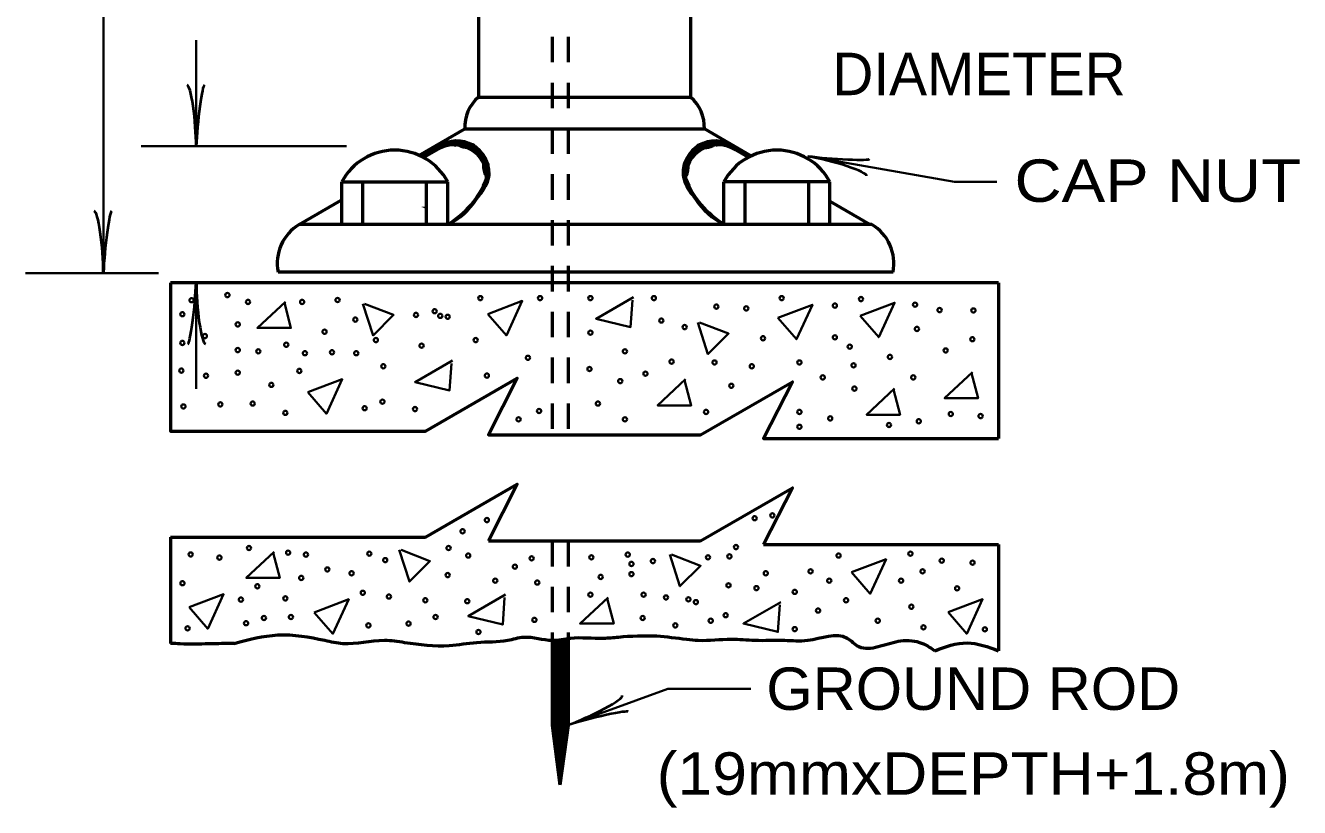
# Model space of a CAD drawing. Extents: x -761 to 95, y 34 to 578.
# Drawn here: x -554.6 to -482.6, y 285.9 to 330.2 of the extents above; entities that cross this region are included whole.
import ezdxf
from ezdxf.enums import TextEntityAlignment as Align

# ---------------------------------------------------------------- set-up
doc = ezdxf.new("R2010")
doc.units = 0
doc.header["$LTSCALE"] = 0.96
doc.linetypes.add('SHORT_DASHED', pattern=[2.7, 1.5, -1.2])
doc.layers.add('1', color=7, linetype='Continuous', lineweight=53)

msp = doc.modelspace()

# ---------------------------------------------------------------- linework, layer by layer
at = {"layer": '1'}
for p, q in [((-517.0193, 467.7038), (-517.0193, 326.125)), ((-529.0193, 336.7251), (-529.0193, 326.125)), ((-529.0193, 326.125), (-517.0193, 326.125)), ((-532.3876, 322.8281), (-529.7949, 324.325)), ((-529.7949, 324.325), (-516.2437, 324.325)), ((-513.6183, 322.8092), (-516.2437, 324.325)), ((-532.2425, 322.7735), (-531.2352, 323.3551)), ((-532.129, 322.7734), (-531.1792, 323.3218)), ((-532.1165, 322.7517), (-531.1667, 323.3001)), ((-532.098, 322.7197), (-531.1482, 323.2681)), ((-513.7656, 322.7197), (-514.7154, 323.2681)), ((-513.7471, 322.7517), (-514.6969, 323.3001)), ((-513.7346, 322.7734), (-514.6844, 323.3218)), ((-513.6211, 322.7735), (-514.6284, 323.3551)), ((-536.748, 318.925), (-536.748, 321.325)), ((-536.748, 321.325), (-530.748, 321.325)), ((-535.548, 318.925), (-535.548, 321.325)), ((-531.948, 318.925), (-531.948, 321.325)), ((-530.748, 318.925), (-530.748, 321.325)), ((-515.1456, 318.925), (-515.1456, 321.325)), ((-509.1456, 321.325), (-515.1456, 321.325)), ((-513.9456, 318.925), (-513.9456, 321.325)), ((-510.3456, 318.925), (-510.3456, 321.325)), ((-509.1456, 318.925), (-509.1456, 321.325)), ((-539.148, 318.925), (-536.7713, 320.2972)), ((-506.8906, 318.925), (-509.1351, 320.2208)), ((-506.7746, 318.925), (-539.148, 318.925)), ((-505.5746, 316.225), (-540.348, 316.225)), ((-499.6193, 315.625), (-546.4193, 315.625)), ((-499.6193, 315.625), (-499.6193, 306.8098)), ((-546.4193, 301.225), (-532.0193, 301.225)), ((-546.4193, 301.225), (-546.4193, 295.225)), ((-528.4575, 301.0174), (-516.4575, 301.0174)), ((-512.8957, 300.8098), (-499.6193, 300.8098)), ((-499.6193, 300.8098), (-499.6193, 294.8098)), ((-524.8487, 295.4027), (-524.8487, 290.6027)), ((-524.8059, 295.4027), (-524.8059, 290.2684)), ((-524.7608, 295.4027), (-524.7608, 289.9162)), ((-524.7157, 295.4027), (-524.7157, 289.564)), ((-524.6706, 295.4027), (-524.6706, 289.2118)), ((-524.6255, 295.4027), (-524.6255, 288.8596)), ((-524.5954, 295.4027), (-524.5954, 288.6245)), ((-524.5503, 295.4027), (-524.5503, 288.2723)), ((-524.5202, 295.4027), (-524.5202, 288.0372)), ((-524.4751, 295.4027), (-524.4751, 287.685)), ((-524.43, 295.4027), (-524.43, 287.3328)), ((-524.3999, 295.4027), (-524.3999, 287.3239)), ((-524.3698, 295.4027), (-524.3698, 287.5426)), ((-524.3247, 295.4027), (-524.3247, 287.8704)), ((-524.2946, 295.4027), (-524.2946, 288.0891)), ((-524.2495, 295.4027), (-524.2495, 288.4168)), ((-524.1894, 295.4027), (-524.1894, 288.8536)), ((-524.1443, 295.4027), (-524.1443, 289.1813)), ((-524.1142, 295.4027), (-524.1142, 289.4)), ((-524.054, 295.4027), (-524.054, 289.8375)), ((-524.024, 295.4027), (-524.024, 290.0555)), ((-523.9487, 295.5049), (-523.9487, 290.6027)), ((-524.8487, 290.6027), (-524.4149, 287.2149)), ((-523.9487, 290.6027), (-524.4149, 287.2149))]:
    msp.add_line(p, q, dxfattribs=at)
at = {"layer": '1', "lineweight": 35}
for p, q in [((-550.2198, 389.2266), (-550.2198, 316.225)), ((-544.9735, 323.3548), (-544.9735, 329.3548)), ((-536.4826, 323.3548), (-548.0895, 323.3548)), ((-547.1104, 316.1577), (-554.6258, 316.1577)), ((-544.9735, 315.625), (-544.9735, 309.625))]:
    msp.add_line(p, q, dxfattribs=at)
at = {"layer": '1', "linetype": 'SHORT_DASHED'}
for p, q in [((-524.8487, 332.125), (-524.8487, 307.0174)), ((-523.9487, 332.125), (-523.9487, 307.0174)), ((-524.8487, 301.0174), (-524.8487, 295.4027)), ((-523.9487, 301.0174), (-523.9487, 295.5049))]:
    msp.add_line(p, q, dxfattribs=at)
at = {"layer": '1', "linetype": 'SHORT_DASHED', "lineweight": 13}
for p, q in [((-524.8487, 307.0174), (-524.8487, 306.9881)), ((-523.9487, 307.0174), (-523.9487, 306.9881))]:
    msp.add_line(p, q, dxfattribs=at)
at = {"layer": '1', "lineweight": 13}
for p, q in [((-524.3987, 290.6027), (-524.3987, 291.0254)), ((-524.8487, 290.6027), (-523.9487, 290.6027)), ((-524.4149, 290.8149), (-524.4149, 287.2149))]:
    msp.add_line(p, q, dxfattribs=at)
at = {"layer": '1', "lineweight": 35}
for points in [[(-510.3841, 322.7822), (-502.1117, 321.3236), (-499.7117, 321.3236)], [(-520.2596, 314.8049), (-522.3694, 313.5918), (-520.4178, 313.1171), (-520.3123, 314.6467)], [(-539.9335, 314.5412), (-541.5158, 313.0643), (-539.617, 313.0643), (-539.9862, 314.4884)], [(-535.5557, 314.4357), (-534.9755, 312.6424), (-533.8151, 313.8028), (-535.4502, 314.4357)], [(-516.6202, 313.3808), (-516.04, 311.5875), (-514.8796, 312.7479), (-516.5147, 313.3808)], [(-530.4921, 311.2183), (-532.6019, 310.0052), (-530.6503, 309.5305), (-530.5448, 311.0601)], [(-501.0824, 310.5641), (-502.6647, 309.0872), (-500.7659, 309.0872), (-501.1351, 310.5113)], [(-517.3059, 310.1634), (-518.8882, 308.6865), (-516.9894, 308.6865), (-517.3586, 310.1106)], [(-505.4911, 309.6359), (-507.0734, 308.159), (-505.1746, 308.159), (-505.5438, 309.5831)], [(-540.5664, 300.4056), (-542.1487, 298.9287), (-540.2499, 298.9287), (-540.6191, 300.3528)], [(-533.4985, 300.511), (-532.9183, 298.7177), (-531.7579, 299.8781), (-533.393, 300.511)], [(-518.2025, 300.2473), (-517.6223, 298.454), (-516.4619, 299.6144), (-518.097, 300.2473)], [(-527.4857, 297.9793), (-529.5955, 296.7662), (-527.6439, 296.2915), (-527.5384, 297.8211)], [(-521.6838, 297.8211), (-523.2661, 296.3442), (-521.3673, 296.3442), (-521.7365, 297.7683)], [(-511.926, 297.5573), (-514.0358, 296.3442), (-512.0842, 295.8695), (-511.9787, 297.3991)], [(-523.9487, 290.6027), (-518.3105, 292.6548), (-513.6138, 292.6548)]]:
    msp.add_lwpolyline(points, dxfattribs=at)
at = {"layer": '1'}
for points in [[(-546.4193, 315.625), (-546.4193, 307.225), (-532.0193, 307.225), (-526.8231, 310.225), (-528.4575, 307.0174), (-516.4575, 307.0174), (-511.2613, 310.0174), (-512.8957, 306.8098), (-499.6193, 306.8098)], [(-516.4575, 307.0174), (-511.2613, 310.0174), (-512.8957, 306.8098)], [(-532.0193, 301.225), (-526.8231, 304.225), (-528.4575, 301.0174)], [(-516.4575, 301.0174), (-511.2613, 304.0174), (-512.8957, 300.8098)]]:
    msp.add_lwpolyline(points, dxfattribs=at)
at = {"layer": '1', "lineweight": 35}
for points in [[(-528.4878, 313.8555), (-527.4329, 312.6424), (-526.5362, 314.594)], [(-512.0842, 313.6446), (-511.0293, 312.4315), (-510.1326, 314.3831)], [(-507.4426, 313.7499), (-506.3877, 312.5368), (-505.491, 314.4884)], [(-538.6676, 309.4249), (-537.6127, 308.2118), (-536.716, 310.1634)], [(-507.9174, 299.2451), (-506.8625, 298.032), (-505.9658, 299.9836)], [(-545.3755, 297.2671), (-544.3206, 296.054), (-543.4239, 298.0056)], [(-538.2984, 296.9771), (-537.2435, 295.764), (-536.3468, 297.7156)], [(-502.4646, 296.9827), (-501.4097, 295.7696), (-500.513, 297.7212)]]:
    msp.add_lwpolyline(points, close=True, dxfattribs=at)
for centre in [(-543.2072, 314.9259), (-528.9098, 314.7521), (-525.5341, 314.7521), (-522.6859, 314.7521), (-519.0993, 314.7521), (-511.8732, 314.7521), (-507.3899, 314.6994), (-545.2375, 314.6359), (-542.0432, 314.5412), (-538.984, 314.5412), (-536.9797, 314.6467), (-531.4943, 314.0137), (-515.5653, 314.2774), (-513.8775, 314.172), (-508.8668, 314.3302), (-504.3307, 314.3829), (-502.9452, 314.0771), (-501.0347, 314.0558), (-545.7558, 313.845), (-542.6233, 313.265), (-535.9776, 313.539), (-532.5492, 313.8027), (-531.1778, 313.75), (-530.7559, 313.6972), (-518.6773, 313.4863), (-544.4834, 312.6056), (-537.7182, 312.8533), (-522.6859, 312.8006), (-517.3587, 313.1171), (-508.8668, 312.5369), (-504.2252, 313.0116), (-545.7558, 312.2208), (-542.6233, 311.8147), (-539.8807, 312.1149), (-534.8172, 312.3786), (-532.2327, 312.0622), (-529.1735, 312.3786), (-512.9281, 312.4841), (-508.0228, 312.0094), (-502.6009, 311.7934), (-501.0927, 312.4315), (-541.4631, 311.7457), (-538.8258, 311.6402), (-537.2962, 311.6929), (-535.9248, 311.6402), (-526.2198, 311.3765), (-520.7343, 311.7457), (-518.0971, 311.1655), (-515.6708, 311.1128), (-510.8711, 311.1128), (-505.7548, 311.4292), (-545.8138, 310.6546), (-544.4216, 310.3645), (-542.6233, 310.5385), (-539.1423, 310.6381), (-534.3952, 310.9018), (-528.5406, 310.3743), (-522.7386, 310.7435), (-519.574, 310.4798), (-513.561, 310.9018), (-507.8119, 310.9545), (-540.7246, 309.8469), (-520.9981, 310.0579), (-514.7214, 309.7941), (-509.5524, 310.2688), (-507.7591, 309.6359), (-504.4362, 310.2688), (-534.448, 308.8975), (-545.6978, 308.6242), (-543.6095, 308.7403), (-541.7795, 308.792), (-539.9335, 308.2645), (-535.4501, 308.5283), (-532.6019, 308.4755), (-525.5869, 308.37), (-522.2639, 308.792), (-516.1455, 308.3173), (-510.8711, 308.3173), (-502.3109, 308.1969), (-526.7472, 307.8953), (-520.7343, 307.8953), (-510.8711, 307.4734), (-509.1305, 307.9481), (-505.8076, 307.5789), (-504.1197, 307.7898), (-500.6286, 308.0809), (-512.4007, 302.4626), (-528.5406, 302.1989), (-513.4028, 302.3044), (-529.9119, 301.5659), (-545.2863, 300.2523), (-541.9905, 300.6165), (-539.7752, 300.3528), (-538.7731, 300.2473), (-535.1864, 300.3001), (-530.7031, 300.6165), (-520.5761, 300.2473), (-514.4577, 300.6693), (-504.5944, 300.3001), (-543.6621, 300.0783), (-534.2898, 299.9309), (-529.5955, 300.1946), (-526.9582, 299.5616), (-526.0088, 300.0363), (-522.6332, 300.0891), (-520.3651, 299.7199), (-519.152, 299.8781), (-516.0401, 300.0891), (-514.8269, 300.1418), (-508.6558, 300.1946), (-502.8238, 299.9043), (-501.0835, 299.7883), (-539.0368, 298.9287), (-537.5599, 299.4034), (-536.1886, 299.1924), (-530.7559, 299.0869), (-522.1057, 298.9814), (-520.3651, 299.1397), (-512.7699, 299.1924), (-510.2381, 299.2979), (-503.9087, 299.2979), (-545.7504, 298.6281), (-541.5158, 298.454), (-535.5556, 298.0848), (-528.0659, 298.7705), (-525.6924, 298.665), (-514.8797, 298.5067), (-513.2973, 298.3485), (-511.1348, 298.1375), (-509.1832, 298.7705), (-505.1219, 298.7705), (-501.9536, 298.338), (-542.4439, 297.6999), (-539.9335, 297.7683), (-534.0788, 297.8738), (-532.0217, 297.6628), (-529.6482, 297.6101), (-522.6859, 297.9793), (-519.6794, 297.9793), (-518.4136, 297.8211), (-517.1477, 297.7156), (-516.7257, 297.5573), (-508.2338, 297.6628), (-541.1466, 296.6607), (-539.617, 296.7134), (-531.4415, 296.7134), (-519.7322, 296.6607), (-515.0379, 296.8189), (-509.8162, 297.0826), (-504.5417, 297.2936), (-545.4604, 296.0757), (-542.1539, 296.3657), (-535.2392, 296.2387), (-532.9711, 296.3442), (-525.8506, 296.5552), (-517.8861, 296.2387), (-515.8818, 296.5024), (-511.1348, 296.0277), (-506.4405, 296.5024), (-503.856, 296.1332), (-500.3874, 296.0177), (-529.0153, 295.8695)]:
    msp.add_circle(centre, 0.12, dxfattribs=at)
at = {"layer": '1'}
for centre, radius, start, end in [((-527.5229, 324.4131), 2.2737, 131.15753, 182.22112), ((-518.5157, 324.4131), 2.2737, 357.77888, 48.84247), ((-530.3929, 321.5897), 1.8354, 357.56619, 122.5437), ((-530.2479, 321.8079), 1.8354, 357.56619, 122.5437), ((-530.2479, 321.8079), 1.8354, 357.56619, 122.5437), ((-515.6157, 321.8079), 1.8354, 57.4563, 182.43381), ((-515.6157, 321.8079), 1.8354, 57.4563, 182.43381), ((-515.4707, 321.5897), 1.8354, 57.4563, 182.43381), ((-533.748, 319.725), 3.4, 28.07249, 151.92751), ((-512.1456, 319.725), 3.4, 28.07249, 151.92751), ((-533.3978, 323.3865), 5.189, 300.70688, 338.8212), ((-530.4427, 322.0183), 2.0488, 321.26362, 351.91119), ((-515.4209, 322.0183), 2.0488, 188.08881, 218.73638), ((-512.4658, 323.3865), 5.189, 201.1788, 239.29312), ((-570.2692, 352.1887), 52.0121, 322.29634, 322.79175), ((-475.5944, 352.1887), 52.0121, 217.20825, 217.70366), ((-534.487, 321.454), 2.8289, 326.68295, 327.02077), ((-532.4449, 322.4675), 3.9279, 295.59515, 327.88518), ((-513.4187, 322.4675), 3.9279, 212.11482, 244.40485), ((-537.8121, 316.7146), 2.5828, 121.14818, 190.92684), ((-508.1105, 316.7146), 2.5828, 349.07316, 58.85182)]:
    msp.add_arc(centre, radius, start, end, dxfattribs=at)
at = {"layer": '1', "lineweight": 40}
for centre, major_axis, ratio, start_param, end_param in [((-545.3051, 324.6642), (0.1874, -2.1428), 0.122415, 0.8963533, 3.1415927), ((-544.7196, 324.6994), (0.2108, 2.1077), 0.07063, 6.2823074, 8.5597026), ((-509.1521, 322.2283), (-2.0777, 0.5566), 0.122415, 3.1415927, 5.386832), ((-509.0158, 322.7988), (2.1123, -0.1584), 0.07063, 4.006668, 6.2840632), ((-550.5514, 317.5344), (0.1874, -2.1428), 0.122415, 0.8963533, 3.1415927), ((-549.9659, 317.5696), (0.2108, 2.1077), 0.07063, 6.2823074, 8.5597026), ((-545.2274, 314.2804), (-0.2108, -2.1077), 0.07063, 6.2823074, 8.5597026), ((-544.6419, 314.3156), (-0.1874, 2.1428), 0.122415, 0.8963533, 3.1415927), ((-522.8316, 291.3621), (-1.9495, -0.909), 0.122415, 0.8963533, 3.1415927), ((-522.5983, 290.824), (2.0527, 0.5228), 0.07063, 6.2823074, 8.5597026)]:
    msp.add_ellipse(centre, major_axis=major_axis, ratio=ratio, start_param=start_param, end_param=end_param, dxfattribs=at)
at = {"layer": '1'}
for points in [[(-529.9008, 319.4829), (-529.7703, 319.6134), (-529.7268, 319.6714), (-529.6398, 319.7874), (-529.5673, 319.8455), (-529.4512, 319.976), (-529.3787, 320.063), (-529.1902, 320.295), (-529.0742, 320.4691), (-528.9726, 320.5851), (-528.9001, 320.6721), (-528.8711, 320.7301), (-528.7841, 320.8171), (-528.7696, 320.8752), (-528.7406, 320.9332), (-528.7116, 320.9912), (-528.6826, 321.0782), (-528.7406, 320.9912), (-528.8131, 320.8897), (-528.8566, 320.8317), (-528.9001, 320.7301), (-528.6826, 321.1362), (-528.6101, 321.2232), (-528.5666, 321.2812), (-528.5521, 321.3828), (-528.6536, 321.2232), (-528.6681, 321.1072), (-528.523, 321.4988), (-528.4795, 321.6148), (-528.494, 321.6148), (-528.494, 321.6728), (-528.5376, 321.7018), (-528.5376, 321.7888), (-528.523, 321.8469), (-528.5085, 321.8469), (-528.5085, 321.8614), (-528.523, 321.9194), (-528.523, 322.0064), (-528.5085, 322.0789), (-528.5521, 322.1224), (-528.5956, 322.1514), (-528.5956, 322.1804), (-528.6101, 322.2384), (-528.6246, 322.2674), (-528.6246, 322.2819), (-528.6246, 322.3545), (-528.6391, 322.4125), (-528.6391, 322.427), (-528.6536, 322.4995), (-528.6681, 322.5285), (-528.6971, 322.601), (-528.7116, 322.601), (-528.7261, 322.63), (-528.7551, 322.659), (-528.8421, 322.746), (-528.8566, 322.8185), (-528.9291, 322.8621), (-528.9726, 322.9201), (-528.9726, 322.9636), (-529.0742, 323.0216), (-529.1177, 323.0361), (-529.2047, 323.0941), (-529.3352, 323.1956), (-529.3642, 323.2391), (-529.4512, 323.2826), (-529.5528, 323.3261), (-529.7268, 323.3551), (-529.8283, 323.3987), (-530.0168, 323.4857), (-530.3794, 323.5437), (-530.4084, 323.5437), (-530.655, 323.5002), (-531.1481, 323.3406), (-530.8145, 323.4857), (-530.6985, 323.5147), (-530.655, 323.5147), (-530.6115, 323.5002), (-530.5099, 323.4857), (-530.3214, 323.4132), (-530.1619, 323.4712), (-529.9733, 323.4277), (-530.3649, 323.4857), (-530.5825, 323.4567), (-530.5099, 323.5872), (-530.3504, 323.6162), (-530.2779, 323.5872), (-530.2054, 323.5727), (-530.1184, 323.5872), (-530.0023, 323.5437), (-529.9298, 323.5292), (-529.8863, 323.5147), (-529.7558, 323.5002), (-529.7413, 323.4857), (-529.6978, 323.4277), (-529.5818, 323.3987), (-529.5382, 323.3842), (-529.5673, 323.3406)], [(-529.5673, 323.3406), (-529.6978, 323.3551), (-529.6978, 323.4712), (-529.6978, 323.4857), (-529.7703, 323.4132), (-529.4512, 323.3551), (-529.3062, 323.2971), (-529.2047, 323.1811), (-529.1177, 323.0941), (-529.0597, 323.0651), (-528.9726, 323.0216), (-528.7986, 322.9056), (-528.7986, 322.8475), (-528.7406, 322.688), (-528.6681, 322.6155), (-528.5666, 322.427), (-528.5085, 322.3835), (-528.4795, 322.1804), (-528.4505, 322.0499), (-528.4795, 321.8614), (-528.6391, 322.4705), (-528.7841, 322.5865), (-528.8566, 322.8475), (-529.0161, 322.9491), (-529.1757, 323.2391), (-528.9581, 322.8185), (-529.2337, 323.1231), (-529.4512, 323.2246), (-529.6108, 323.4422), (-529.2337, 323.2391), (-529.0452, 323.0941), (-528.8856, 322.7605), (-528.6681, 322.3254), (-528.4505, 321.7888), (-528.494, 321.7018), (-528.7116, 322.6735), (-528.7116, 322.746), (-528.8421, 322.833), (-529.2337, 323.1521), (-529.4512, 323.4277), (-529.5382, 323.4857), (-529.7413, 323.5147), (-530.0168, 323.5872), (-530.5389, 323.5002), (-530.1474, 323.4857), (-529.9733, 323.4277), (-529.8573, 323.4277), (-529.8138, 323.4567), (-529.5963, 323.3697), (-529.3497, 323.2681), (-529.2772, 323.1956), (-529.1032, 323.0361), (-528.9291, 322.8475), (-528.8421, 322.7315), (-528.6826, 322.5285), (-528.4795, 322.0934), (-528.6681, 322.63), (-528.9726, 323.0941), (-529.1902, 323.3116), (-529.3642, 323.4277), (-529.4077, 323.3987), (-529.1467, 323.1376), (-529.0887, 323.1376), (-529.2917, 323.2971), (-529.5237, 323.2826), (-530.4519, 323.5727)], [(-516.2963, 323.3406), (-516.1658, 323.3551), (-516.1658, 323.4712), (-516.1658, 323.4857), (-516.0933, 323.4132), (-516.4124, 323.3551), (-516.5574, 323.2971), (-516.6589, 323.1811), (-516.7459, 323.0941), (-516.8039, 323.0651), (-516.891, 323.0216), (-517.065, 322.9056), (-517.065, 322.8475), (-517.123, 322.688), (-517.1955, 322.6155), (-517.297, 322.427), (-517.3551, 322.3835), (-517.3841, 322.1804), (-517.4131, 322.0499), (-517.3841, 321.8614), (-517.2245, 322.4705), (-517.0795, 322.5865), (-517.007, 322.8475), (-516.8475, 322.9491), (-516.6879, 323.2391), (-516.9055, 322.8185), (-516.6299, 323.1231), (-516.4124, 323.2246), (-516.2528, 323.4422), (-516.6299, 323.2391), (-516.8184, 323.0941), (-516.978, 322.7605), (-517.1955, 322.3254), (-517.4131, 321.7888), (-517.3696, 321.7018), (-517.152, 322.6735), (-517.152, 322.746), (-517.0215, 322.833), (-516.6299, 323.1521), (-516.4124, 323.4277), (-516.3254, 323.4857), (-516.1223, 323.5147), (-515.8468, 323.5872), (-515.3247, 323.5002), (-515.7162, 323.4857), (-515.8903, 323.4277), (-516.0063, 323.4277), (-516.0498, 323.4567), (-516.2673, 323.3697), (-516.5139, 323.2681), (-516.5864, 323.1956), (-516.7604, 323.0361), (-516.9345, 322.8475), (-517.0215, 322.7315), (-517.181, 322.5285), (-517.3841, 322.0934), (-517.1955, 322.63), (-516.891, 323.0941), (-516.6734, 323.3116), (-516.4994, 323.4277), (-516.4559, 323.3987), (-516.7169, 323.1376), (-516.7749, 323.1376), (-516.5719, 323.2971), (-516.3399, 323.2826), (-515.4117, 323.5727)], [(-515.9628, 319.4829), (-516.0933, 319.6134), (-516.1368, 319.6714), (-516.2238, 319.7874), (-516.2963, 319.8455), (-516.4124, 319.976), (-516.4849, 320.063), (-516.6734, 320.295), (-516.7894, 320.4691), (-516.891, 320.5851), (-516.9635, 320.6721), (-516.9925, 320.7301), (-517.0795, 320.8171), (-517.094, 320.8752), (-517.123, 320.9332), (-517.152, 320.9912), (-517.181, 321.0782), (-517.123, 320.9912), (-517.0505, 320.8897), (-517.007, 320.8317), (-516.9635, 320.7301), (-517.181, 321.1362), (-517.2535, 321.2232), (-517.297, 321.2812), (-517.3115, 321.3828), (-517.21, 321.2232), (-517.1955, 321.1072), (-517.3406, 321.4988), (-517.3841, 321.6148), (-517.3696, 321.6148), (-517.3696, 321.6728), (-517.326, 321.7018), (-517.326, 321.7888), (-517.3406, 321.8469), (-517.3551, 321.8469), (-517.3551, 321.8614), (-517.3406, 321.9194), (-517.3406, 322.0064), (-517.3551, 322.0789), (-517.3115, 322.1224), (-517.268, 322.1514), (-517.268, 322.1804), (-517.2535, 322.2384), (-517.239, 322.2674), (-517.239, 322.2819), (-517.239, 322.3545), (-517.2245, 322.4125), (-517.2245, 322.427), (-517.21, 322.4995), (-517.1955, 322.5285), (-517.1665, 322.601), (-517.152, 322.601), (-517.1375, 322.63), (-517.1085, 322.659), (-517.0215, 322.746), (-517.007, 322.8185), (-516.9345, 322.8621), (-516.891, 322.9201), (-516.891, 322.9636), (-516.7894, 323.0216), (-516.7459, 323.0361), (-516.6589, 323.0941), (-516.5284, 323.1956), (-516.4994, 323.2391), (-516.4124, 323.2826), (-516.3108, 323.3261), (-516.1368, 323.3551), (-516.0353, 323.3987), (-515.8468, 323.4857), (-515.4842, 323.5437), (-515.4552, 323.5437), (-515.2086, 323.5002), (-514.7155, 323.3406), (-515.0491, 323.4857), (-515.1651, 323.5147), (-515.2086, 323.5147), (-515.2521, 323.5002), (-515.3537, 323.4857), (-515.5422, 323.4132), (-515.7017, 323.4712), (-515.8903, 323.4277), (-515.4987, 323.4857), (-515.2811, 323.4567), (-515.3537, 323.5872), (-515.5132, 323.6162), (-515.5857, 323.5872), (-515.6582, 323.5727), (-515.7452, 323.5872), (-515.8613, 323.5437), (-515.9338, 323.5292), (-515.9773, 323.5147), (-516.1078, 323.5002), (-516.1223, 323.4857), (-516.1658, 323.4277), (-516.2818, 323.3987), (-516.3254, 323.3842), (-516.2963, 323.3406)], [(-542.8193, 295.225), (-540.3512, 295.7016), (-537.7046, 295.4009), (-536.682, 295.2204), (-534.3362, 295.4009), (-533.1933, 295.2806), (-530.667, 295.1001), (-529.1031, 295.2806), (-527.3587, 295.4009), (-526.4565, 295.5813), (-524.8324, 295.4009), (-523.8098, 295.5212), (-521.9452, 295.5212), (-521.1031, 295.5813), (-518.9377, 295.6415), (-517.2535, 295.461), (-516.5918, 295.4009), (-514.7271, 295.461), (-513.4038, 295.4009), (-511.7196, 295.4009), (-510.3963, 295.4009), (-508.1708, 295.5212), (-507.5091, 295.04), (-506.4264, 295.04), (-505.2835, 295.3407), (-504.0805, 295.2806), (-503.2193, 294.8098)], [(-542.8193, 295.225), (-544.2567, 295.1943), (-545.8809, 295.1943), (-546.4193, 295.225)], [(-503.2193, 294.8098), (-501.388, 295.2523), (-499.6193, 294.8098)]]:
    msp.add_spline(points, degree=3, dxfattribs=at)

# ---------------------------------------------------------------- texts
msp.add_text('DIAMETER', height=2.4, dxfattribs=at).set_placement((-500.7166, 326.2342), align=Align.CENTER)
at = {"layer": '1', "width": 1.15}
msp.add_text('CAP NUT', height=2.4, dxfattribs=at).set_placement((-498.711, 320.1982))
at = {"layer": '1'}
for s, width, p in [('GROUND ROD', 1.05, (-501.0409, 291.46)), ('(19mmxDEPTH+1.8m)', 1.1, (-501.0408, 286.66))]:
    msp.add_text(s, height=2.4, dxfattribs=dict(at, width=width)).set_placement(p, align=Align.CENTER)

doc.saveas('drawing.dxf')
